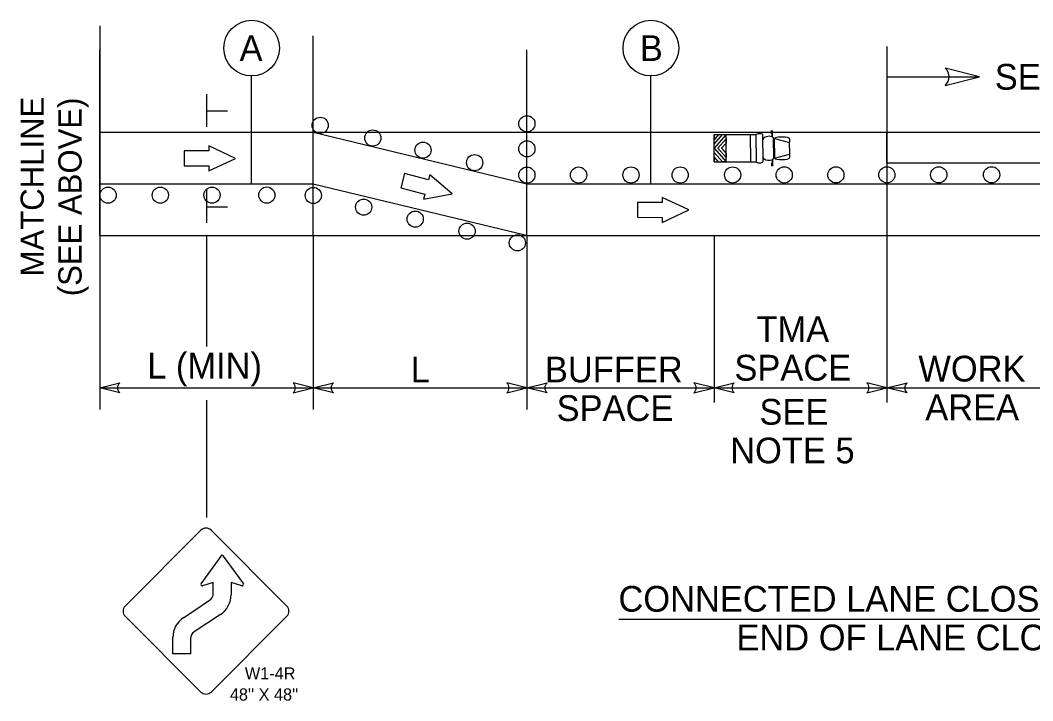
# Model space of a CAD drawing. Extents: x 1379436 to 1387057, y 792703 to 795604.
# Drawn here: x 1386126 to 1386649, y 794781 to 795132 of the extents above; entities that cross this region are included whole.
import ezdxf

# ---------------------------------------------------------------- set-up
doc = ezdxf.new("R2010")
doc.units = 0
for name, color, linetype in [('Black Area Fill Shapes', 7, 'Continuous'), ('Default', 7, 'Continuous'), ('DEV DIRECTION OF TRAFFIC FLOW ARROW CELL', 7, 'Continuous'), ('Gray Area Fill Shapes', 7, 'Continuous'), ('Prop Mkg Skp Wht', 7, 'Continuous'), ('Prop Mkg Solid White Lane Line', 7, 'Continuous'), ('Prop Mkg Solid Yellow Edge Line', 7, 'Continuous'), ('Scratch_Level_5', 7, 'Continuous'), ('Text', 7, 'Continuous')]:
    doc.layers.add(name, color=color, linetype=linetype)

msp = doc.modelspace()

# ---------------------------------------------------------------- linework, layer by layer
at = {"layer": 'Black Area Fill Shapes'}
for p, q in [((1386219.63, 794841.45), (1386230.51, 794856.38)), ((1386230.51, 794856.38), (1386241.46, 794841.45)), ((1386225.95, 794842.12), (1386220.36, 794840.36)), ((1386225.95, 794836.38), (1386225.95, 794842.12)), ((1386240.71, 794840.36), (1386235.14, 794842.12)), ((1386235.14, 794842.12), (1386235.14, 794835.79)), ((1386210.51, 794823.88), (1386224.04, 794832.85)), ((1386229.63, 794825.5), (1386216.03, 794816.53)), ((1386205.07, 794805.29), (1386205.07, 794813.67)), ((1386214.19, 794813), (1386214.19, 794805.29)), ((1386214.19, 794805.29), (1386205.07, 794805.29))]:
    msp.add_line(p, q, dxfattribs=at)
for centre in [(1386281.16, 795078.08), (1386387.94, 795078.87), (1386308.34, 795071.52), (1386334.27, 795065.26), (1386387.94, 795065.93), (1386360.97, 795058.81), (1386414.64, 795052.4), (1386441.73, 795052.42), (1386467.12, 795052.44), (1386494.2, 795052.46), (1386520.87, 795052.47), (1386547.55, 795052.49), (1386573.89, 795052.51), (1386600.69, 795052.53), (1386627.98, 795052.55), (1386171.59, 795042.01), (1386198.59, 795042.03), (1386225.26, 795042.04), (1386253.58, 795042.06), (1386277.59, 795041.88), (1386303.63, 795035.84), (1386330.25, 795029.66), (1386357.04, 795023.44), (1386383.03, 795017.4)]:
    msp.add_circle(centre, 4.18, dxfattribs=at)
for centre, radius, start, end in [((1386220.21, 794841.04), 0.695, 143.9078, 282.5697), ((1386240.87, 794841.04), 0.695, 257.4303, 36.0922), ((1386221.74, 794836.38), 4.2, 303.5775, 0), ((1386222.84, 794835.76), 12.29, 303.5774, 0), ((1386217.33, 794813.66), 12.29, 123.5774, 180), ((1386218.39, 794813), 4.2, 123.5772, 180)]:
    msp.add_arc(centre, radius, start, end, dxfattribs=at)
at = {"layer": 'Default'}
for p, q in [((1386167.25, 795129.4), (1386167.25, 794966.32)), ((1386573.89, 795118.73), (1386573.89, 795058.54)), ((1386573.89, 795111.19), (1386573.89, 795047.86)), ((1386245.74, 795047.86), (1386245.74, 795103.58)), ((1386451.98, 795047.86), (1386451.98, 795103.58))]:
    msp.add_line(p, q, dxfattribs=at)
for centre in [(1386245.74, 795117.95), (1386451.98, 795117.95)]:
    msp.add_circle(centre, 14.37, dxfattribs=at)
at = {"layer": 'DEV DIRECTION OF TRAFFIC FLOW ARROW CELL'}
for p, q in [((1386210.83, 795064.84), (1386210.82, 795057.13)), ((1386223.6, 795064.83), (1386210.83, 795064.84)), ((1386237.35, 795060.96), (1386223.6, 795067.45)), ((1386223.6, 795067.45), (1386223.6, 795064.83)), ((1386223.59, 795054.5), (1386237.35, 795060.96)), ((1386210.82, 795057.13), (1386223.59, 795057.12)), ((1386223.59, 795057.12), (1386223.59, 795054.5)), ((1386324.79, 795053.29), (1386322.79, 795045.84)), ((1386337.13, 795049.98), (1386324.79, 795053.29)), ((1386337.81, 795052.51), (1386337.13, 795049.98)), ((1386349.41, 795042.68), (1386337.81, 795052.51)), ((1386322.79, 795045.84), (1386335.13, 795042.53)), ((1386334.45, 795040), (1386349.41, 795042.68)), ((1386335.13, 795042.53), (1386334.45, 795040)), ((1386457.78, 795038.28), (1386445, 795038.29)), ((1386445, 795038.29), (1386445, 795030.58)), ((1386471.53, 795034.41), (1386457.78, 795040.9)), ((1386457.78, 795040.9), (1386457.78, 795038.28)), ((1386457.77, 795027.94), (1386471.53, 795034.41)), ((1386445, 795030.58), (1386457.77, 795030.57)), ((1386457.77, 795030.57), (1386457.77, 795027.94))]:
    msp.add_line(p, q, dxfattribs=at)
at = {"layer": 'Gray Area Fill Shapes'}
msp.add_lwpolyline([(1386573.89, 795074.47), (1386665.77, 795074.47), (1386665.77, 795058.54), (1386573.89, 795058.54)], close=True, dxfattribs=at)
at = {"layer": 'Prop Mkg Skp Wht'}
msp.add_line((1386167.25, 795047.86), (1386167.25, 795047.86), dxfattribs=at)
at = {"layer": 'Prop Mkg Solid White Lane Line'}
for p, q in [((1386222.42, 795094.08), (1386222.42, 795077.23)), ((1386222.42, 795085.59), (1386233.34, 795085.59)), ((1386484.59, 795073.27), (1386506.42, 795073.27)), ((1386484.59, 795059.15), (1386484.59, 795073.27)), ((1386484.59, 795073.27), (1386484.59, 795070.58)), ((1386484.59, 795073.27), (1386484.59, 795070.58)), ((1386484.59, 795073.27), (1386484.59, 795070.58)), ((1386484.59, 795073.27), (1386484.59, 795070.58)), ((1386484.59, 795070.58), (1386484.59, 795073.27)), ((1386484.59, 795073.27), (1386486.99, 795073.27)), ((1386486.99, 795073.27), (1386484.59, 795070.58)), ((1386484.59, 795068.39), (1386488.96, 795073.27)), ((1386490.85, 795073.27), (1386484.59, 795066.21)), ((1386488.96, 795073.27), (1386490.85, 795073.27)), ((1386490.85, 795059.15), (1386490.85, 795073.27)), ((1386503.44, 795066.21), (1386503.44, 795073.27)), ((1386506.42, 795066.21), (1386506.42, 795073.27)), ((1386509.77, 795066.21), (1386509.77, 795073.27)), ((1386514.28, 795073.7), (1386514.28, 795075.45)), ((1386514.57, 795072.03), (1386514.57, 795075.45)), ((1386514.79, 795072.03), (1386514.79, 795075.45)), ((1386484.59, 795066.21), (1386484.59, 795068.39)), ((1386486.55, 795066.21), (1386490.85, 795071.08)), ((1386490.85, 795068.9), (1386488.45, 795066.21)), ((1386490.85, 795071.08), (1386490.85, 795068.9)), ((1386515.37, 795066.21), (1386515.37, 795071.3)), ((1386515.88, 795071.3), (1386523.52, 795069.19)), ((1386515.88, 795066.21), (1386515.88, 795071.3)), ((1386523.52, 795066.21), (1386523.52, 795069.19)), ((1386484.59, 795066.21), (1386490.85, 795059.15)), ((1386484.59, 795064.1), (1386484.59, 795066.21)), ((1386488.96, 795059.15), (1386484.59, 795064.1)), ((1386490.85, 795061.41), (1386486.55, 795066.21)), ((1386488.52, 795066.21), (1386490.85, 795063.59)), ((1386490.85, 795063.59), (1386490.85, 795061.41)), ((1386503.44, 795066.21), (1386503.44, 795059.15)), ((1386506.42, 795066.21), (1386506.42, 795059.15)), ((1386509.77, 795066.21), (1386509.77, 795059.15)), ((1386515.37, 795066.21), (1386515.37, 795061.12)), ((1386515.88, 795066.21), (1386515.88, 795061.12)), ((1386515.88, 795061.12), (1386523.52, 795063.23)), ((1386523.52, 795066.21), (1386523.52, 795063.23)), ((1386484.59, 795061.84), (1386484.59, 795059.15)), ((1386486.99, 795059.15), (1386484.59, 795061.84)), ((1386484.59, 795059.15), (1386506.42, 795059.15)), ((1386484.59, 795059.15), (1386486.99, 795059.15)), ((1386490.85, 795059.15), (1386488.96, 795059.15)), ((1386514.28, 795058.71), (1386514.28, 795057.04)), ((1386514.57, 795060.39), (1386514.57, 795057.04)), ((1386514.79, 795060.39), (1386514.79, 795057.04)), ((1386167.25, 795047.86), (1386277.59, 795047.86)), ((1386277.59, 795047.86), (1386387.8, 795021.29)), ((1386222.42, 795044.55), (1386222.42, 795027.7)), ((1386222.42, 795036.05), (1386233.34, 795036.05)), ((1386167.25, 795021.25), (1386841.41, 795021.25)), ((1386263.94, 794824.69), (1386224.76, 794785.51))]:
    msp.add_line(p, q, dxfattribs=at)
for points in [[(1386604, 795098.69), (1386621.77, 795103.14), (1386604, 795107.58)], [(1386604, 795098.69), (1386621.77, 795103.14), (1386604, 795107.58)], [(1386177.64, 794939.93), (1386167.25, 794942.53), (1386177.64, 794945.13)], [(1386177.64, 794939.93), (1386167.25, 794942.53), (1386177.64, 794945.13)], [(1386267.2, 794939.93), (1386277.59, 794942.53), (1386267.2, 794945.13)], [(1386267.2, 794939.93), (1386277.59, 794942.53), (1386267.2, 794945.13)], [(1386287.98, 794939.93), (1386277.59, 794942.53), (1386287.98, 794945.13)], [(1386287.98, 794939.93), (1386277.59, 794942.53), (1386287.98, 794945.13)], [(1386377.54, 794939.93), (1386387.94, 794942.53), (1386377.54, 794945.13)], [(1386377.54, 794939.93), (1386387.94, 794942.53), (1386377.54, 794945.13)], [(1386398.33, 794939.93), (1386387.94, 794942.53), (1386398.33, 794945.13)], [(1386398.33, 794939.93), (1386387.94, 794942.53), (1386398.33, 794945.13)], [(1386474.2, 794939.93), (1386484.59, 794942.53), (1386474.2, 794945.13)], [(1386474.2, 794939.93), (1386484.59, 794942.53), (1386474.2, 794945.13)], [(1386494.98, 794939.93), (1386484.59, 794942.53), (1386494.98, 794945.13)], [(1386494.98, 794939.93), (1386484.59, 794942.53), (1386494.98, 794945.13)], [(1386563.5, 794939.93), (1386573.89, 794942.53), (1386563.5, 794945.13)], [(1386563.5, 794939.93), (1386573.89, 794942.53), (1386563.5, 794945.13)], [(1386584.29, 794939.93), (1386573.89, 794942.53), (1386584.29, 794945.13)], [(1386584.29, 794939.93), (1386573.89, 794942.53), (1386584.29, 794945.13)], [(1386180.4, 794829.87), (1386219.58, 794869.05)], [(1386224.76, 794869.05), (1386263.94, 794829.87)], [(1386219.58, 794785.51), (1386180.4, 794824.69)]]:
    msp.add_lwpolyline(points, dxfattribs=at)
msp.add_circle((1386387.94, 795052.38), 4.18, dxfattribs=at)
for centre, radius, start, end in [((1386600.09, 795103.14), 5.92, 311.3264, 48.6736), ((1386600.09, 795103.14), 5.92, 311.3264, 48.6736), ((1386521.64, 795070.21), 2.12, 331.8801, 28.1199), ((1386521.64, 795062.22), 2.12, 331.8801, 28.1199), ((1386179.92, 794942.53), 3.46, 131.3264, 228.6736), ((1386179.92, 794942.53), 3.46, 131.3264, 228.6736), ((1386264.91, 794942.53), 3.46, 311.3264, 48.6736), ((1386264.91, 794942.53), 3.46, 311.3264, 48.6736), ((1386290.27, 794942.53), 3.46, 131.3264, 228.6736), ((1386290.27, 794942.53), 3.46, 131.3264, 228.6736), ((1386375.26, 794942.53), 3.46, 311.3264, 48.6736), ((1386375.26, 794942.53), 3.46, 311.3264, 48.6736), ((1386400.62, 794942.53), 3.46, 131.3264, 228.6736), ((1386400.62, 794942.53), 3.46, 131.3264, 228.6736), ((1386471.91, 794942.53), 3.46, 311.3264, 48.6736), ((1386471.91, 794942.53), 3.46, 311.3264, 48.6736), ((1386497.27, 794942.53), 3.46, 131.3264, 228.6736), ((1386497.27, 794942.53), 3.46, 131.3264, 228.6736), ((1386561.21, 794942.53), 3.46, 311.3264, 48.6736), ((1386561.21, 794942.53), 3.46, 311.3264, 48.6736), ((1386586.57, 794942.53), 3.46, 131.3264, 228.6736), ((1386586.57, 794942.53), 3.46, 131.3264, 228.6736), ((1386222.17, 794866.46), 3.66, 89.9935, 135), ((1386222.17, 794866.46), 3.66, 44.987, 89.9935), ((1386182.99, 794827.28), 3.66, 135, 225), ((1386261.35, 794827.28), 3.66, 315, 45), ((1386222.17, 794788.1), 3.66, 225, 270), ((1386222.17, 794788.1), 3.66, 270, 315)]:
    msp.add_arc(centre, radius, start, end, dxfattribs=at)
for centre, major_axis, ratio, start_param, end_param in [((1386508.12, 795073.28), (1.67, 0), 0.269913, 0, 3.141593), ((1386512.6, 795070.95), (2.8, 0.35), 0.503092, 0, 3.141593), ((1386519.69, 795071.26), (3.82, -0.04), 0.2034, 0, 3.141593), ((1386508.12, 795059.16), (1.67, 0), 0.269913, 3.141593, 6.283185), ((1386512.6, 795061.48), (2.8, -0.35), 0.503092, 3.141593, 6.283185), ((1386519.69, 795061.18), (3.82, 0.04), 0.2034, 3.141593, 6.283185)]:
    msp.add_ellipse(centre, major_axis=major_axis, ratio=ratio, start_param=start_param, end_param=end_param, dxfattribs=at)
at = {"layer": 'Prop Mkg Solid Yellow Edge Line'}
for p, q in [((1386167.25, 795074.47), (1386841.41, 795074.47)), ((1386277.59, 795074.47), (1386387.94, 795047.86)), ((1386387.94, 795047.86), (1386707.5, 795047.86))]:
    msp.add_line(p, q, dxfattribs=at)
at = {"layer": 'Scratch_Level_5'}
for p, q in [((1386277.59, 795021.25), (1386277.59, 795124.35)), ((1386167.25, 795021.25), (1386167.25, 795117.11)), ((1386387.94, 795021.25), (1386387.94, 795117.11))]:
    msp.add_line(p, q, dxfattribs=at)
at = {"layer": 'Text'}
for p, q in [((1386573.89, 795103.14), (1386621.77, 795103.14)), ((1386573.89, 795058.54), (1386573.89, 794935.06)), ((1386167.25, 795021.25), (1386167.25, 794931.38)), ((1386222.42, 795021.25), (1386222.42, 794963.96)), ((1386277.59, 795021.25), (1386277.59, 794931.38)), ((1386387.96, 795021.25), (1386387.94, 794931.38)), ((1386484.59, 795021.25), (1386484.59, 794935.06)), ((1386167.25, 794942.53), (1386277.59, 794942.53)), ((1386277.59, 794942.53), (1386387.94, 794942.53)), ((1386312.44, 794942.53), (1386387.94, 794942.53)), ((1386387.94, 794942.53), (1386484.59, 794942.53)), ((1386484.59, 794942.53), (1386573.89, 794942.53)), ((1386573.89, 794942.53), (1386665.77, 794942.53)), ((1386222.42, 794936.12), (1386222.42, 794875.63)), ((1386781.55, 794822.93), (1386435.35, 794822.93))]:
    msp.add_line(p, q, dxfattribs=at)

# ---------------------------------------------------------------- texts
at = {"layer": 'Default'}
for s, p in [('MATCHLINE', (1386138.4, 795000.09)), ('(SEE ABOVE)', (1386157.9, 794989.86))]:
    msp.add_text(s, height=12, rotation=90, dxfattribs=at).set_placement(p)
at = {"layer": 'Prop Mkg Solid White Lane Line'}
for s, height, p in [('W1-4R', 6.273, (1386242.26, 794792)), ("48'' X 48''", 6.2732, (1386234.5, 794781.1))]:
    msp.add_text(s, height=height, dxfattribs=at).set_placement(p)
at = {"layer": 'Text'}
for s, height, p in [('A', 13.31, (1386239.52, 795111.3)), ('B', 13.31, (1386446.28, 795111.3)), ('SEE TMP SHEETS', 13.3038, (1386629.63, 795096.48)), ('TMA', 13.304, (1386506.53, 794966.24)), ('L (MIN)', 13.304, (1386191.79, 794947.35)), ('L', 13.3, (1386327.93, 794945.37)), ('BUFFER ', 13.304, (1386397.26, 794945.38)), ('SPACE', 13.304, (1386495.14, 794946.29)), ('WORK ', 13.304, (1386590.15, 794945.81)), ('SPACE', 13.304, (1386403.29, 794925.43)), ('AREA', 13.304, (1386593.72, 794925.85)), ('SEE ', 13.304, (1386508.06, 794923.52)), ('NOTE 5', 13.304, (1386492.96, 794903.57)), ('CONNECTED LANE CLOSURE DEVICE', 13.3038, (1386435.24, 794826.97)), ('END OF LANE CLOSURE', 13.3038, (1386496.19, 794807.01))]:
    msp.add_text(s, height=height, dxfattribs=at).set_placement(p)

doc.saveas('drawing.dxf')
